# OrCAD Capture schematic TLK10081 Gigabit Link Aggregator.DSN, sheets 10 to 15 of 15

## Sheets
10 S10 CLOCK CONTROL: size B
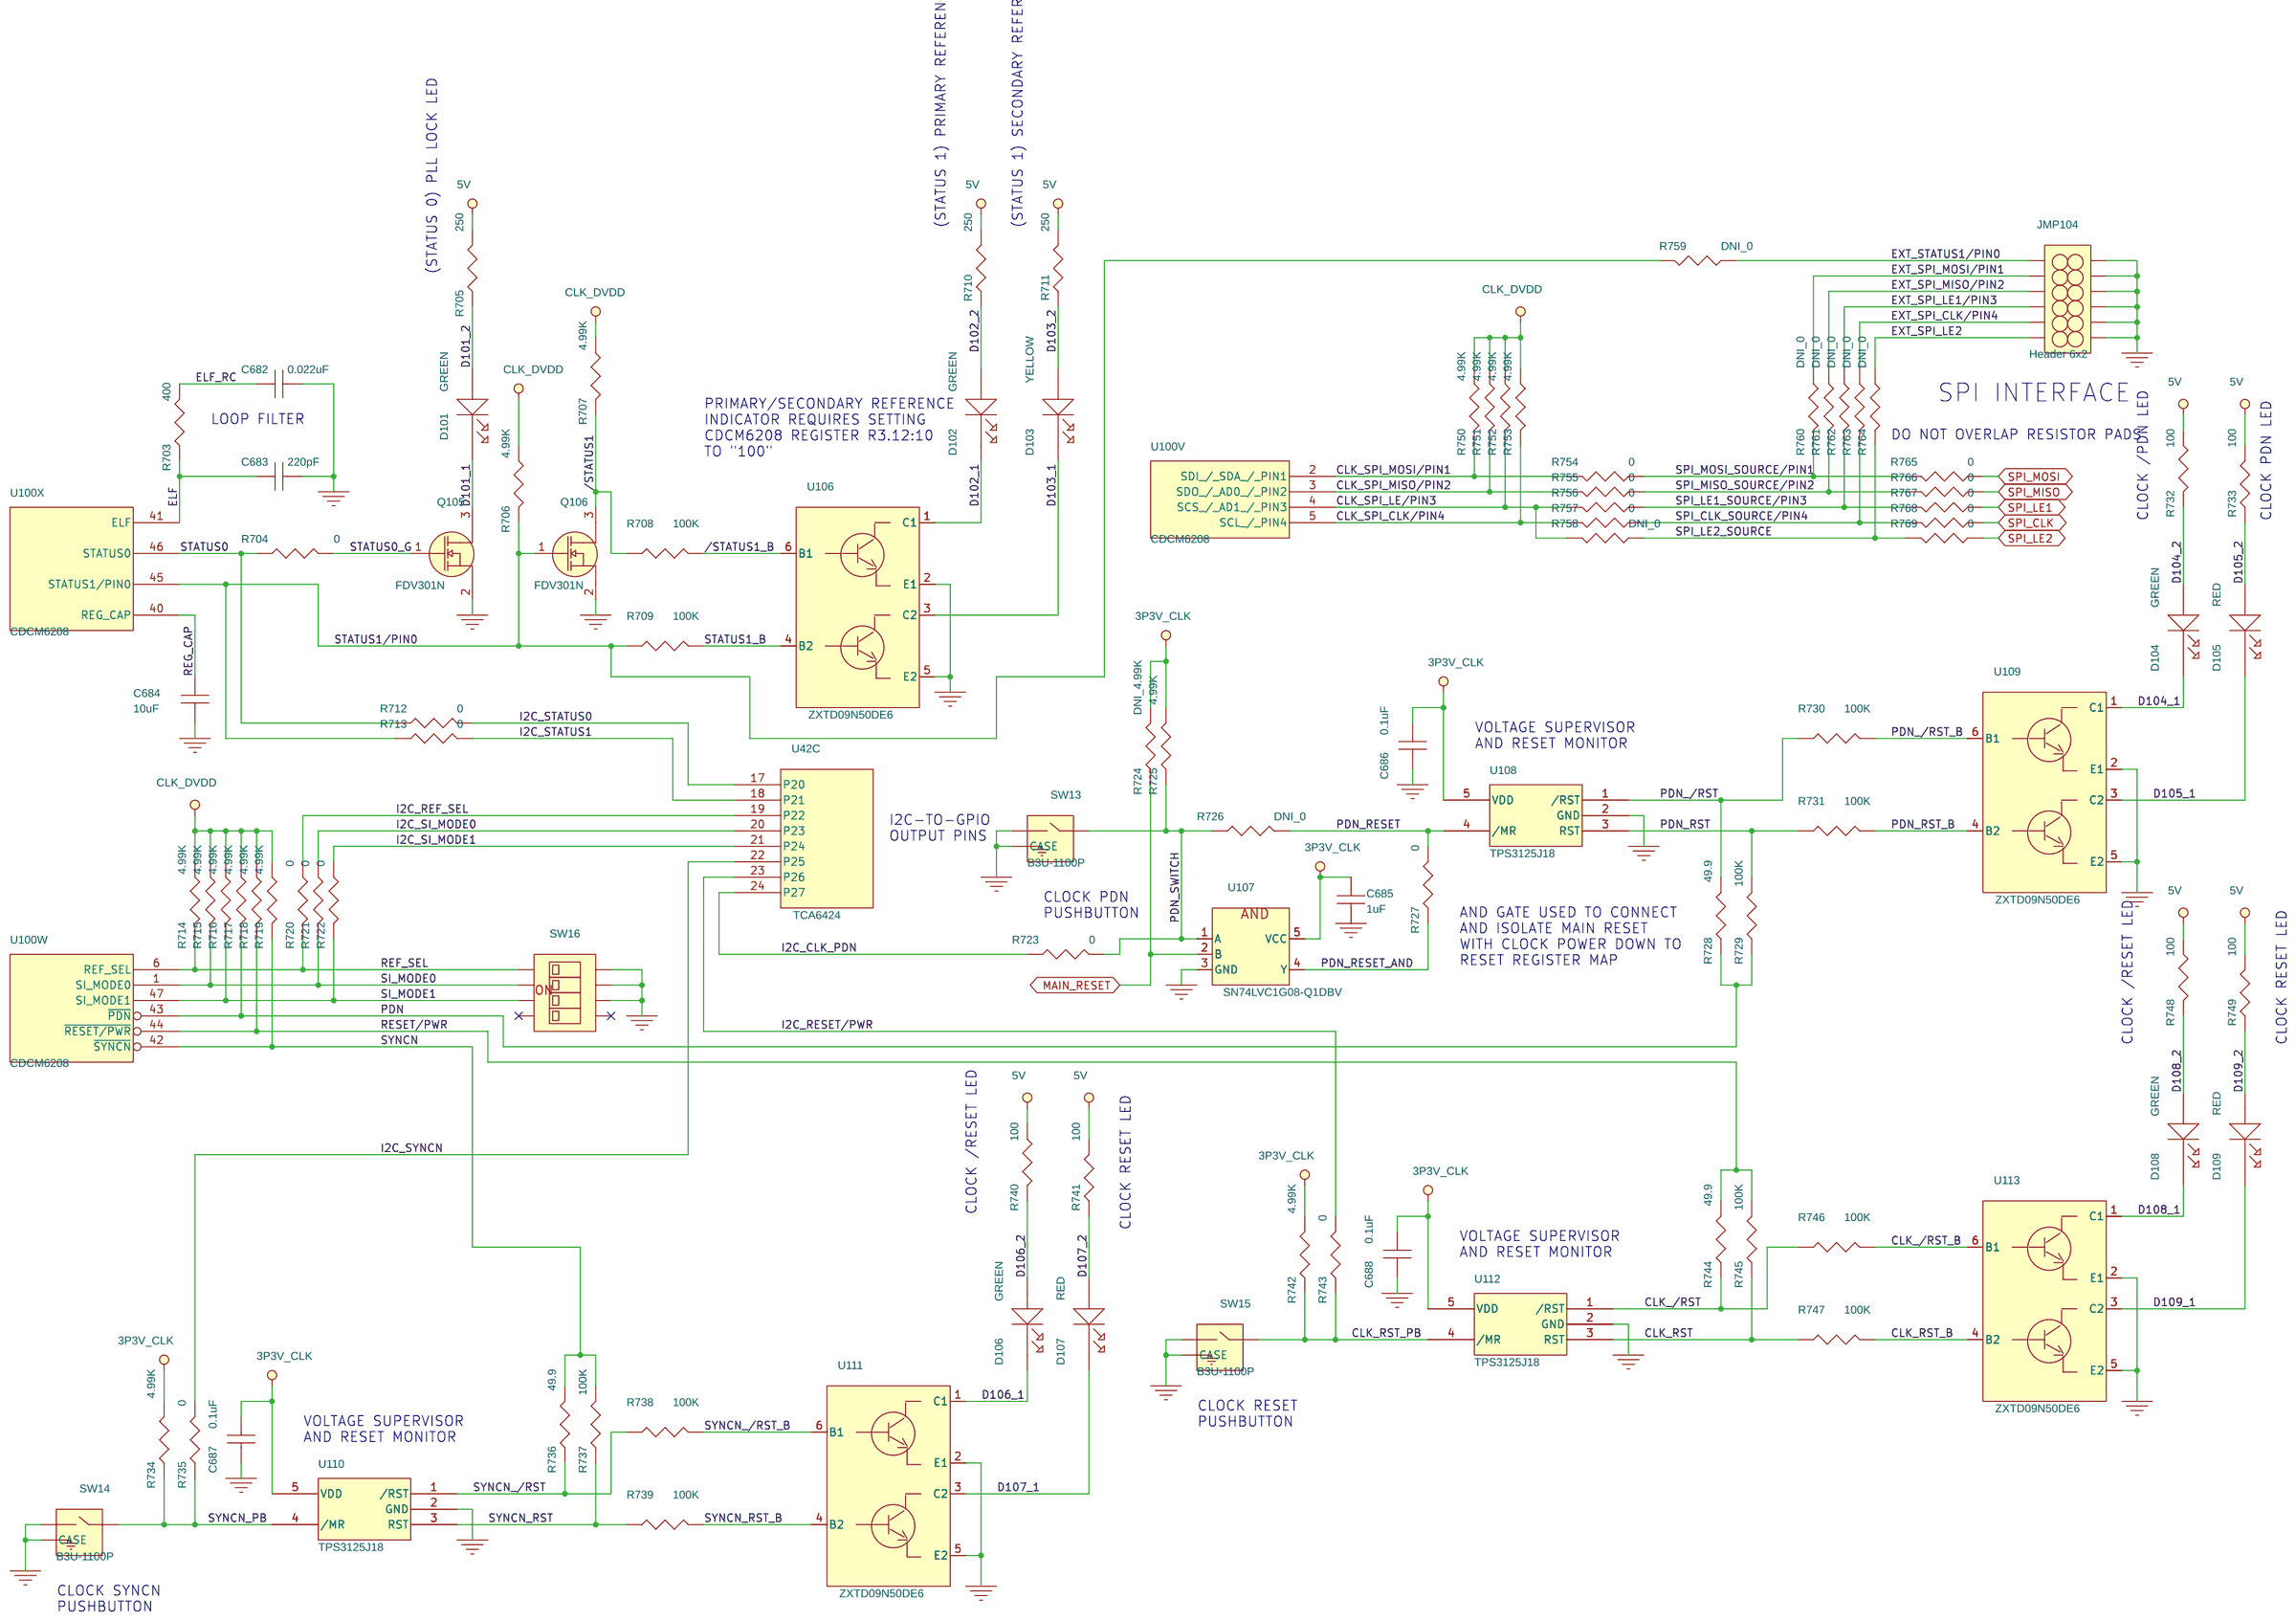
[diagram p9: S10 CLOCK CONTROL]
11 S12 LOW SPEED DATA SIGNALS: size B
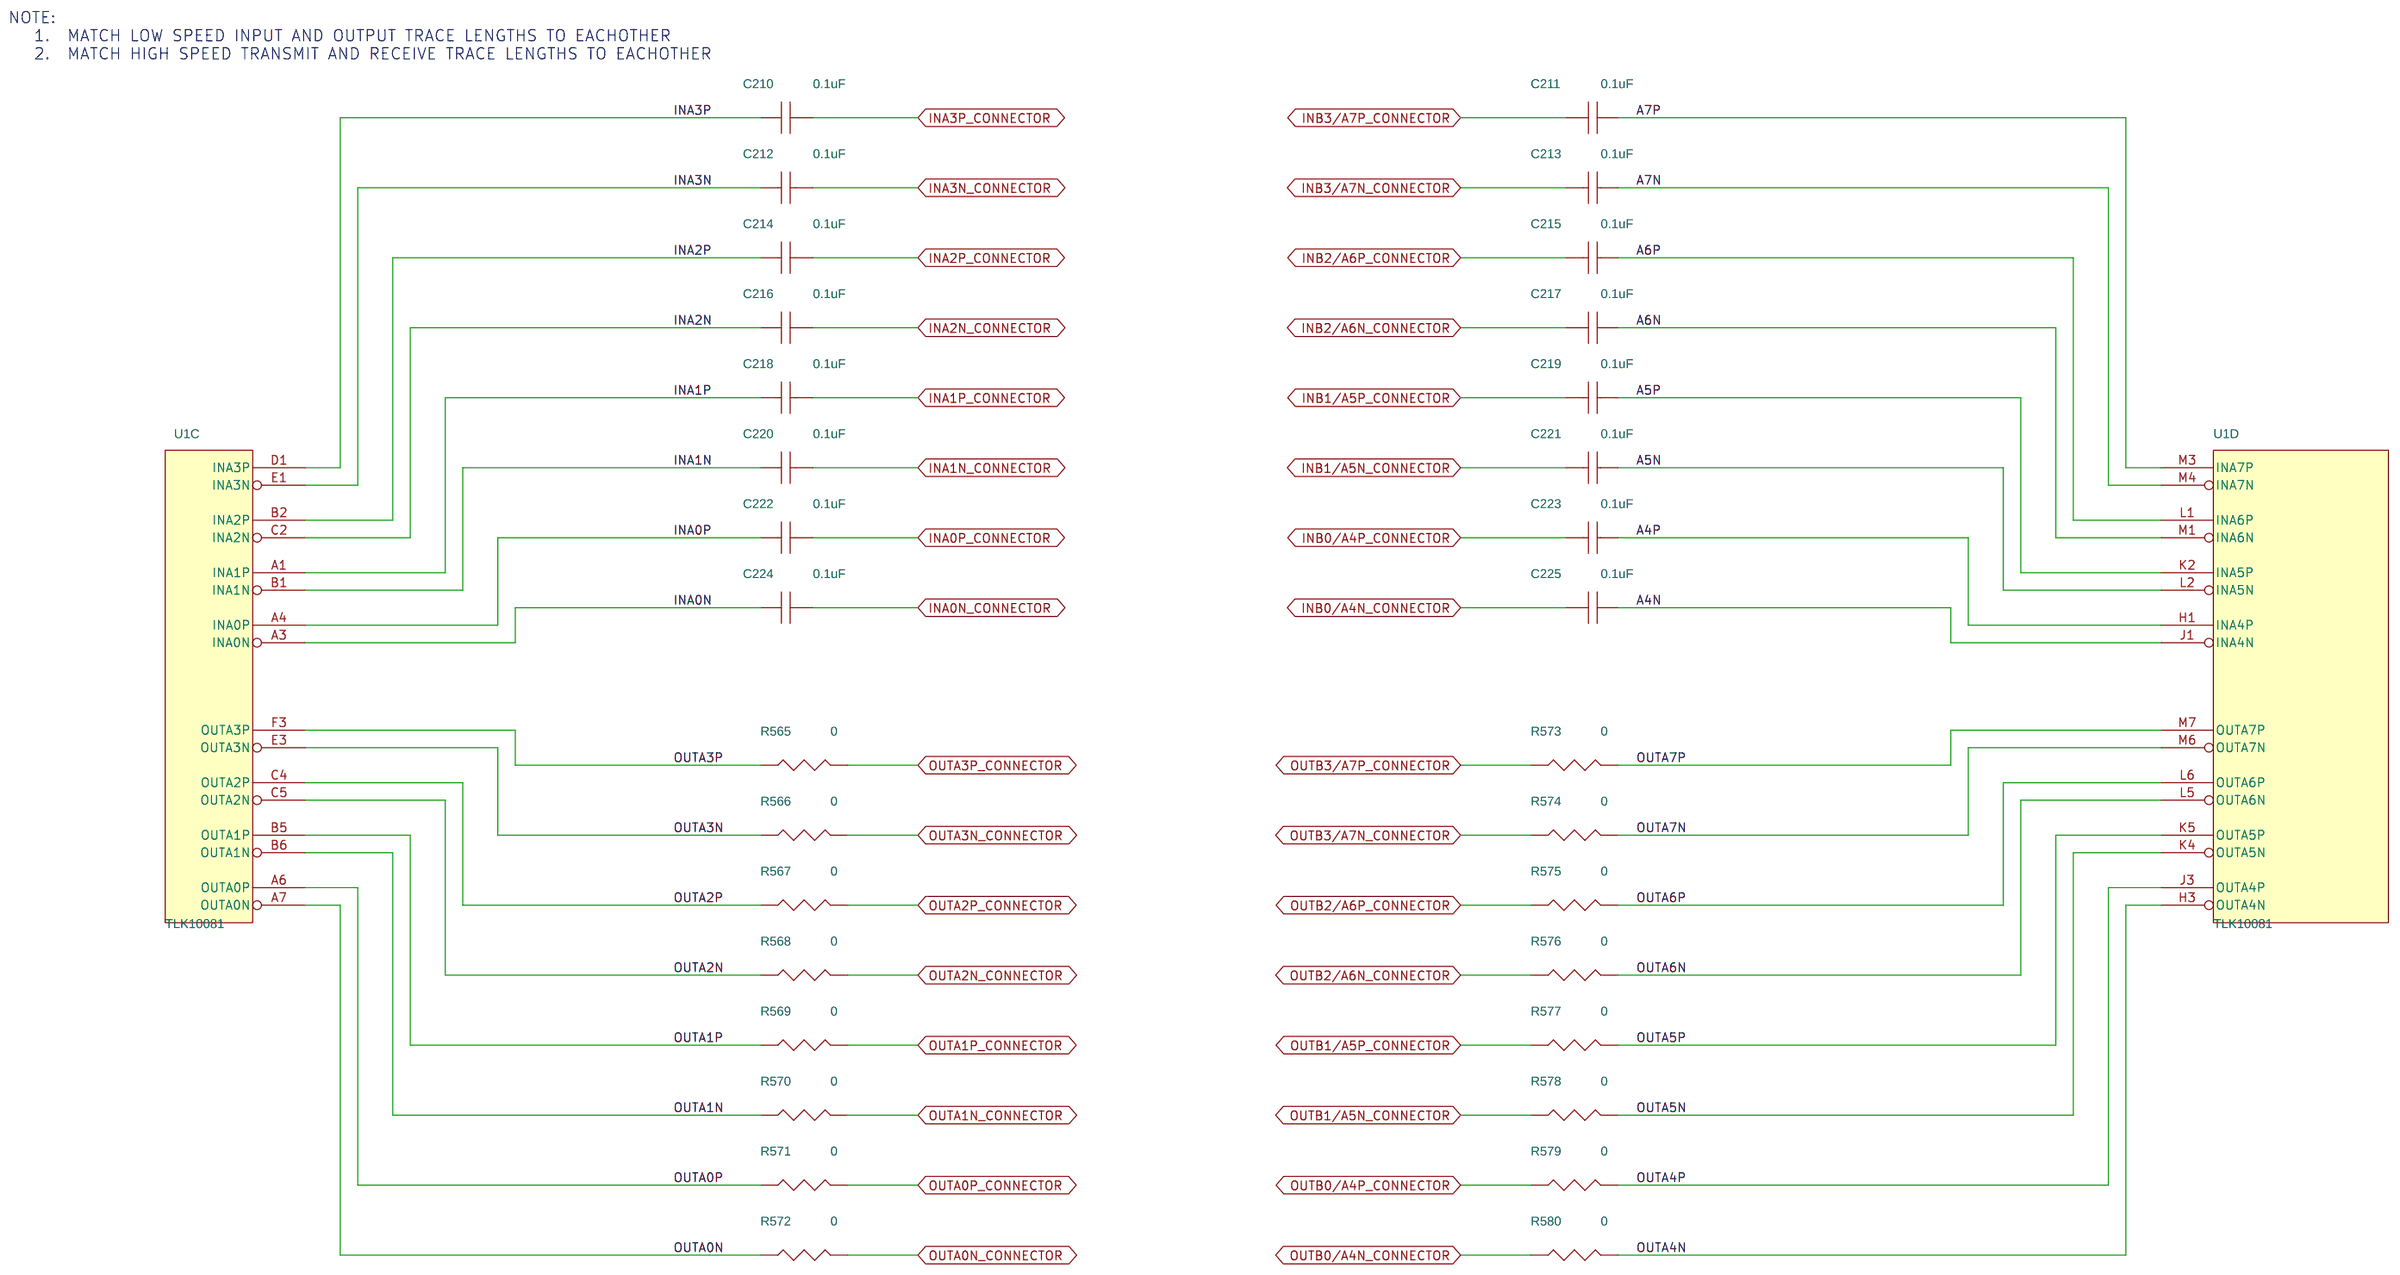
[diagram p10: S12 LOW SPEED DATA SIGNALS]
12 S13 HIGH SPEED DATA SIGNALS: size B
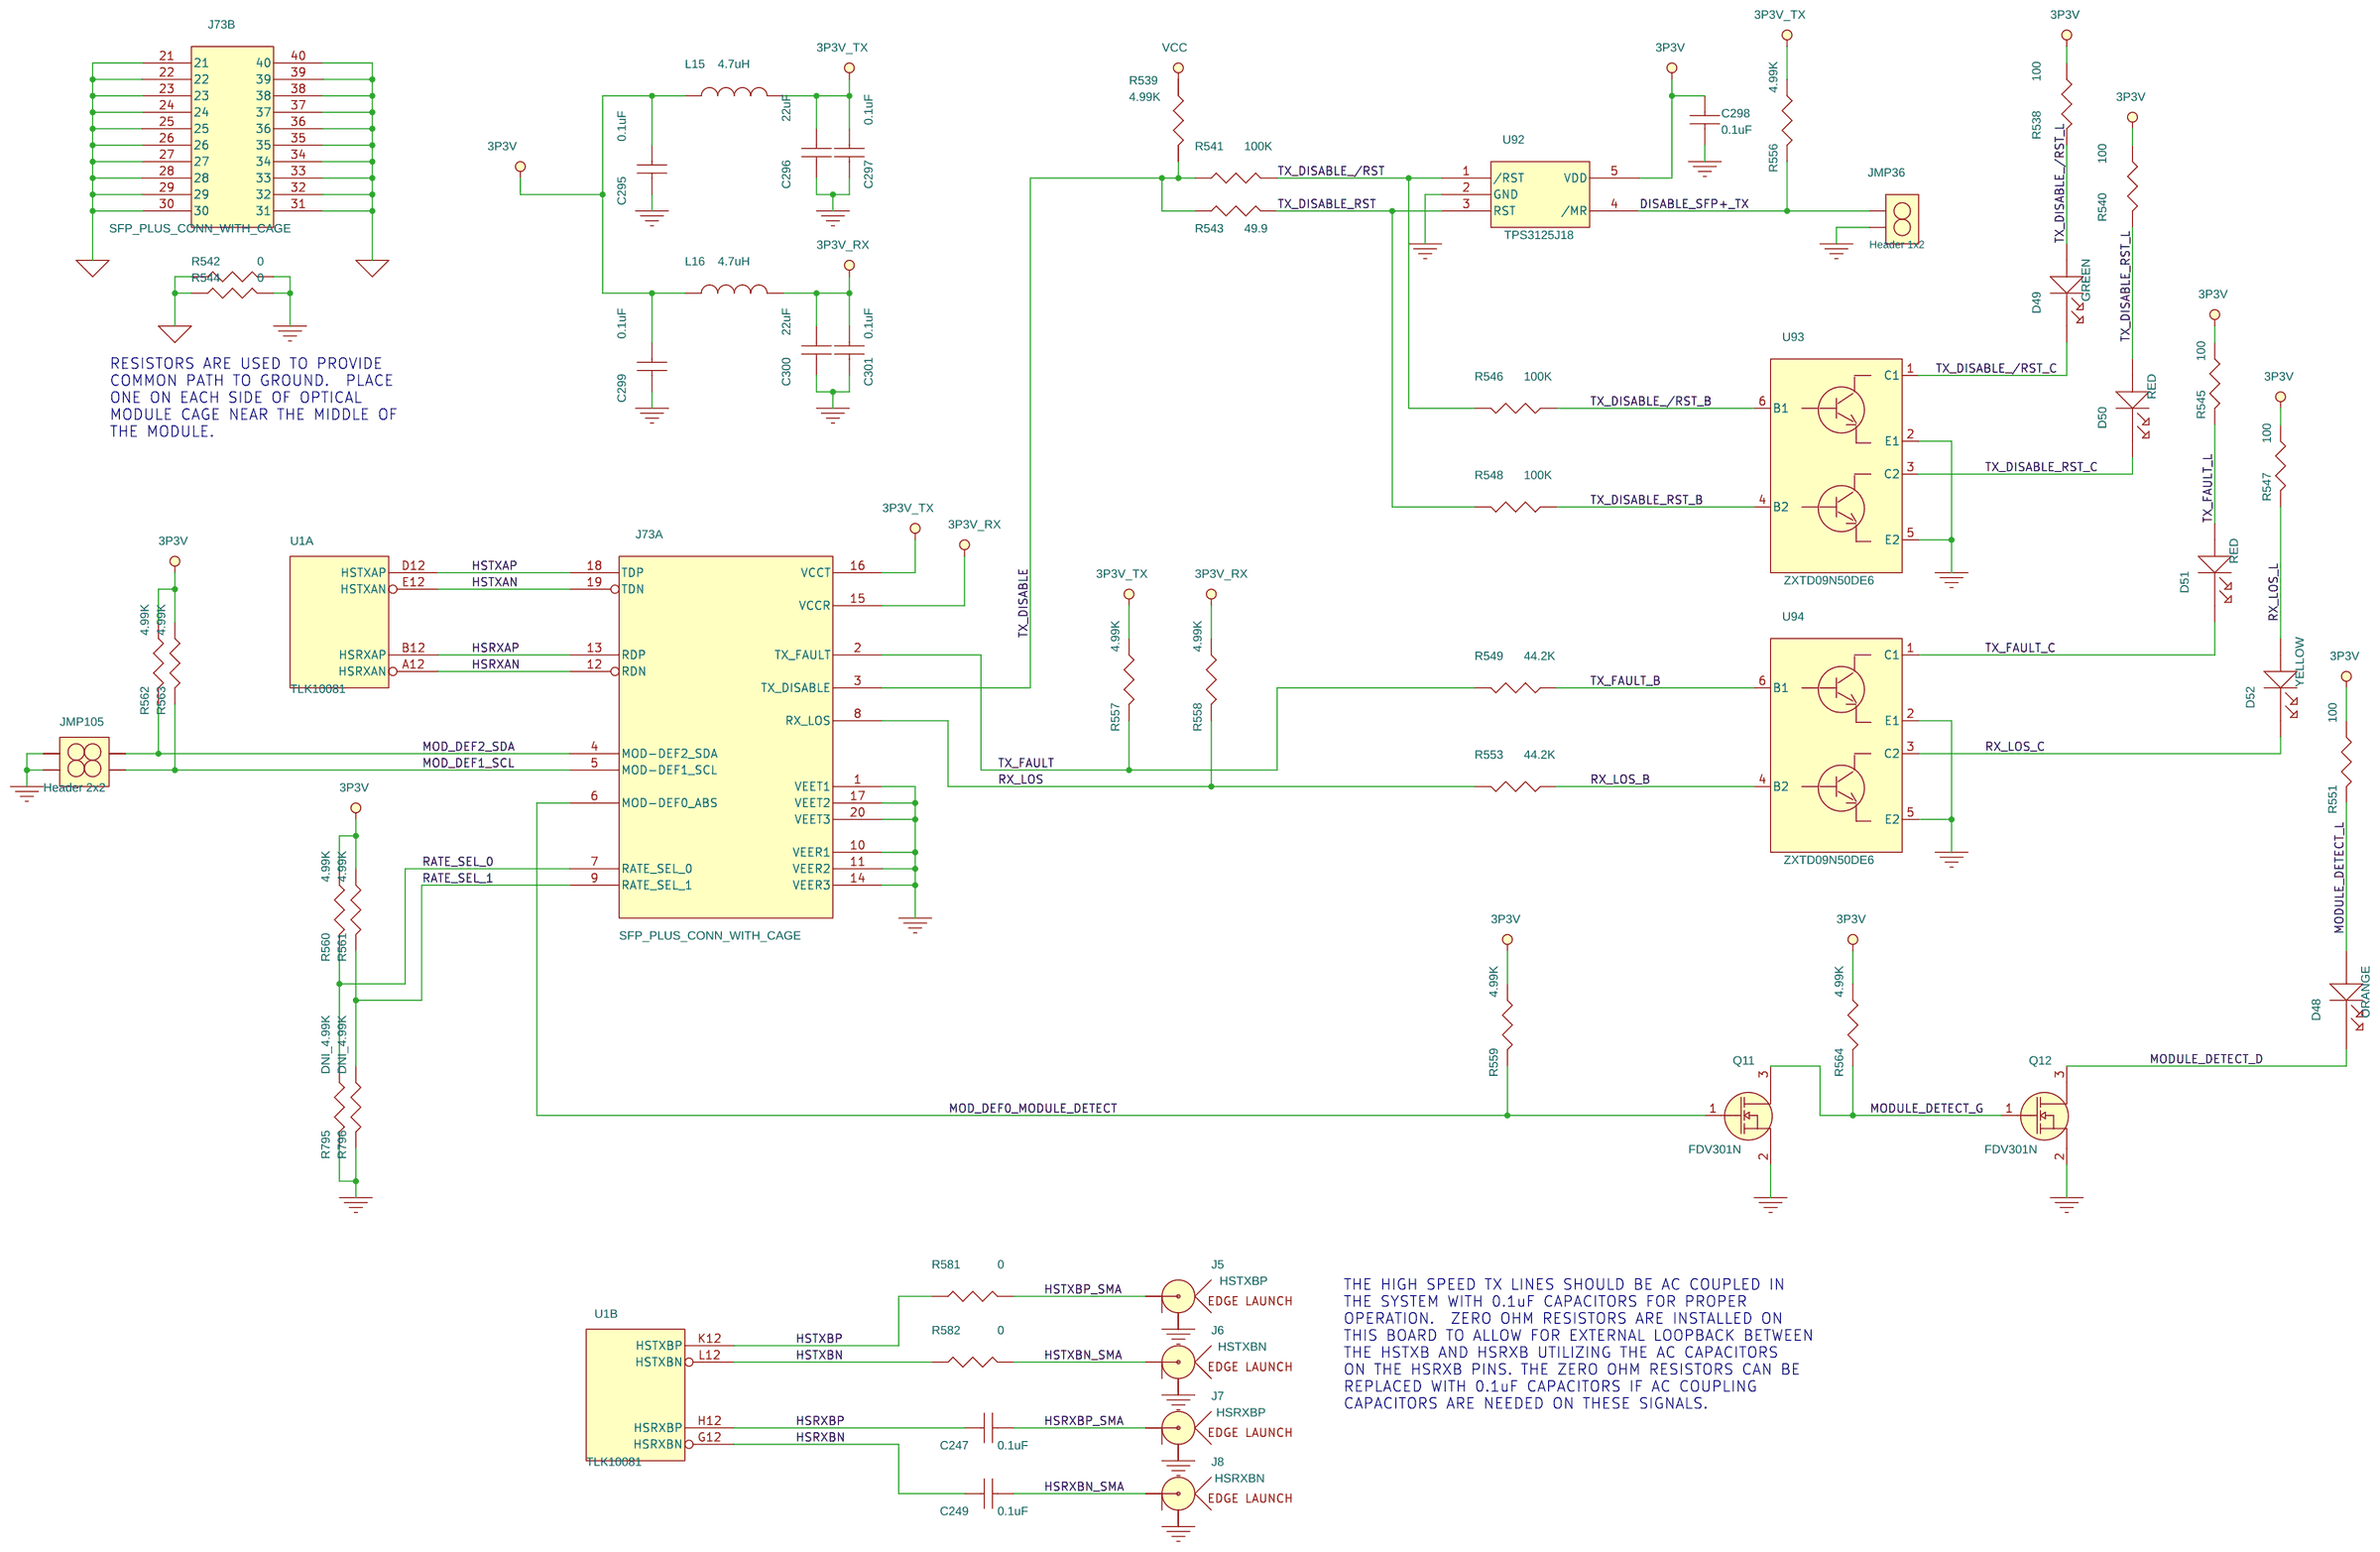
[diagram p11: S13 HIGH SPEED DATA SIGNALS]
13 S11 CRYSTAL OSCILLATORS: size B
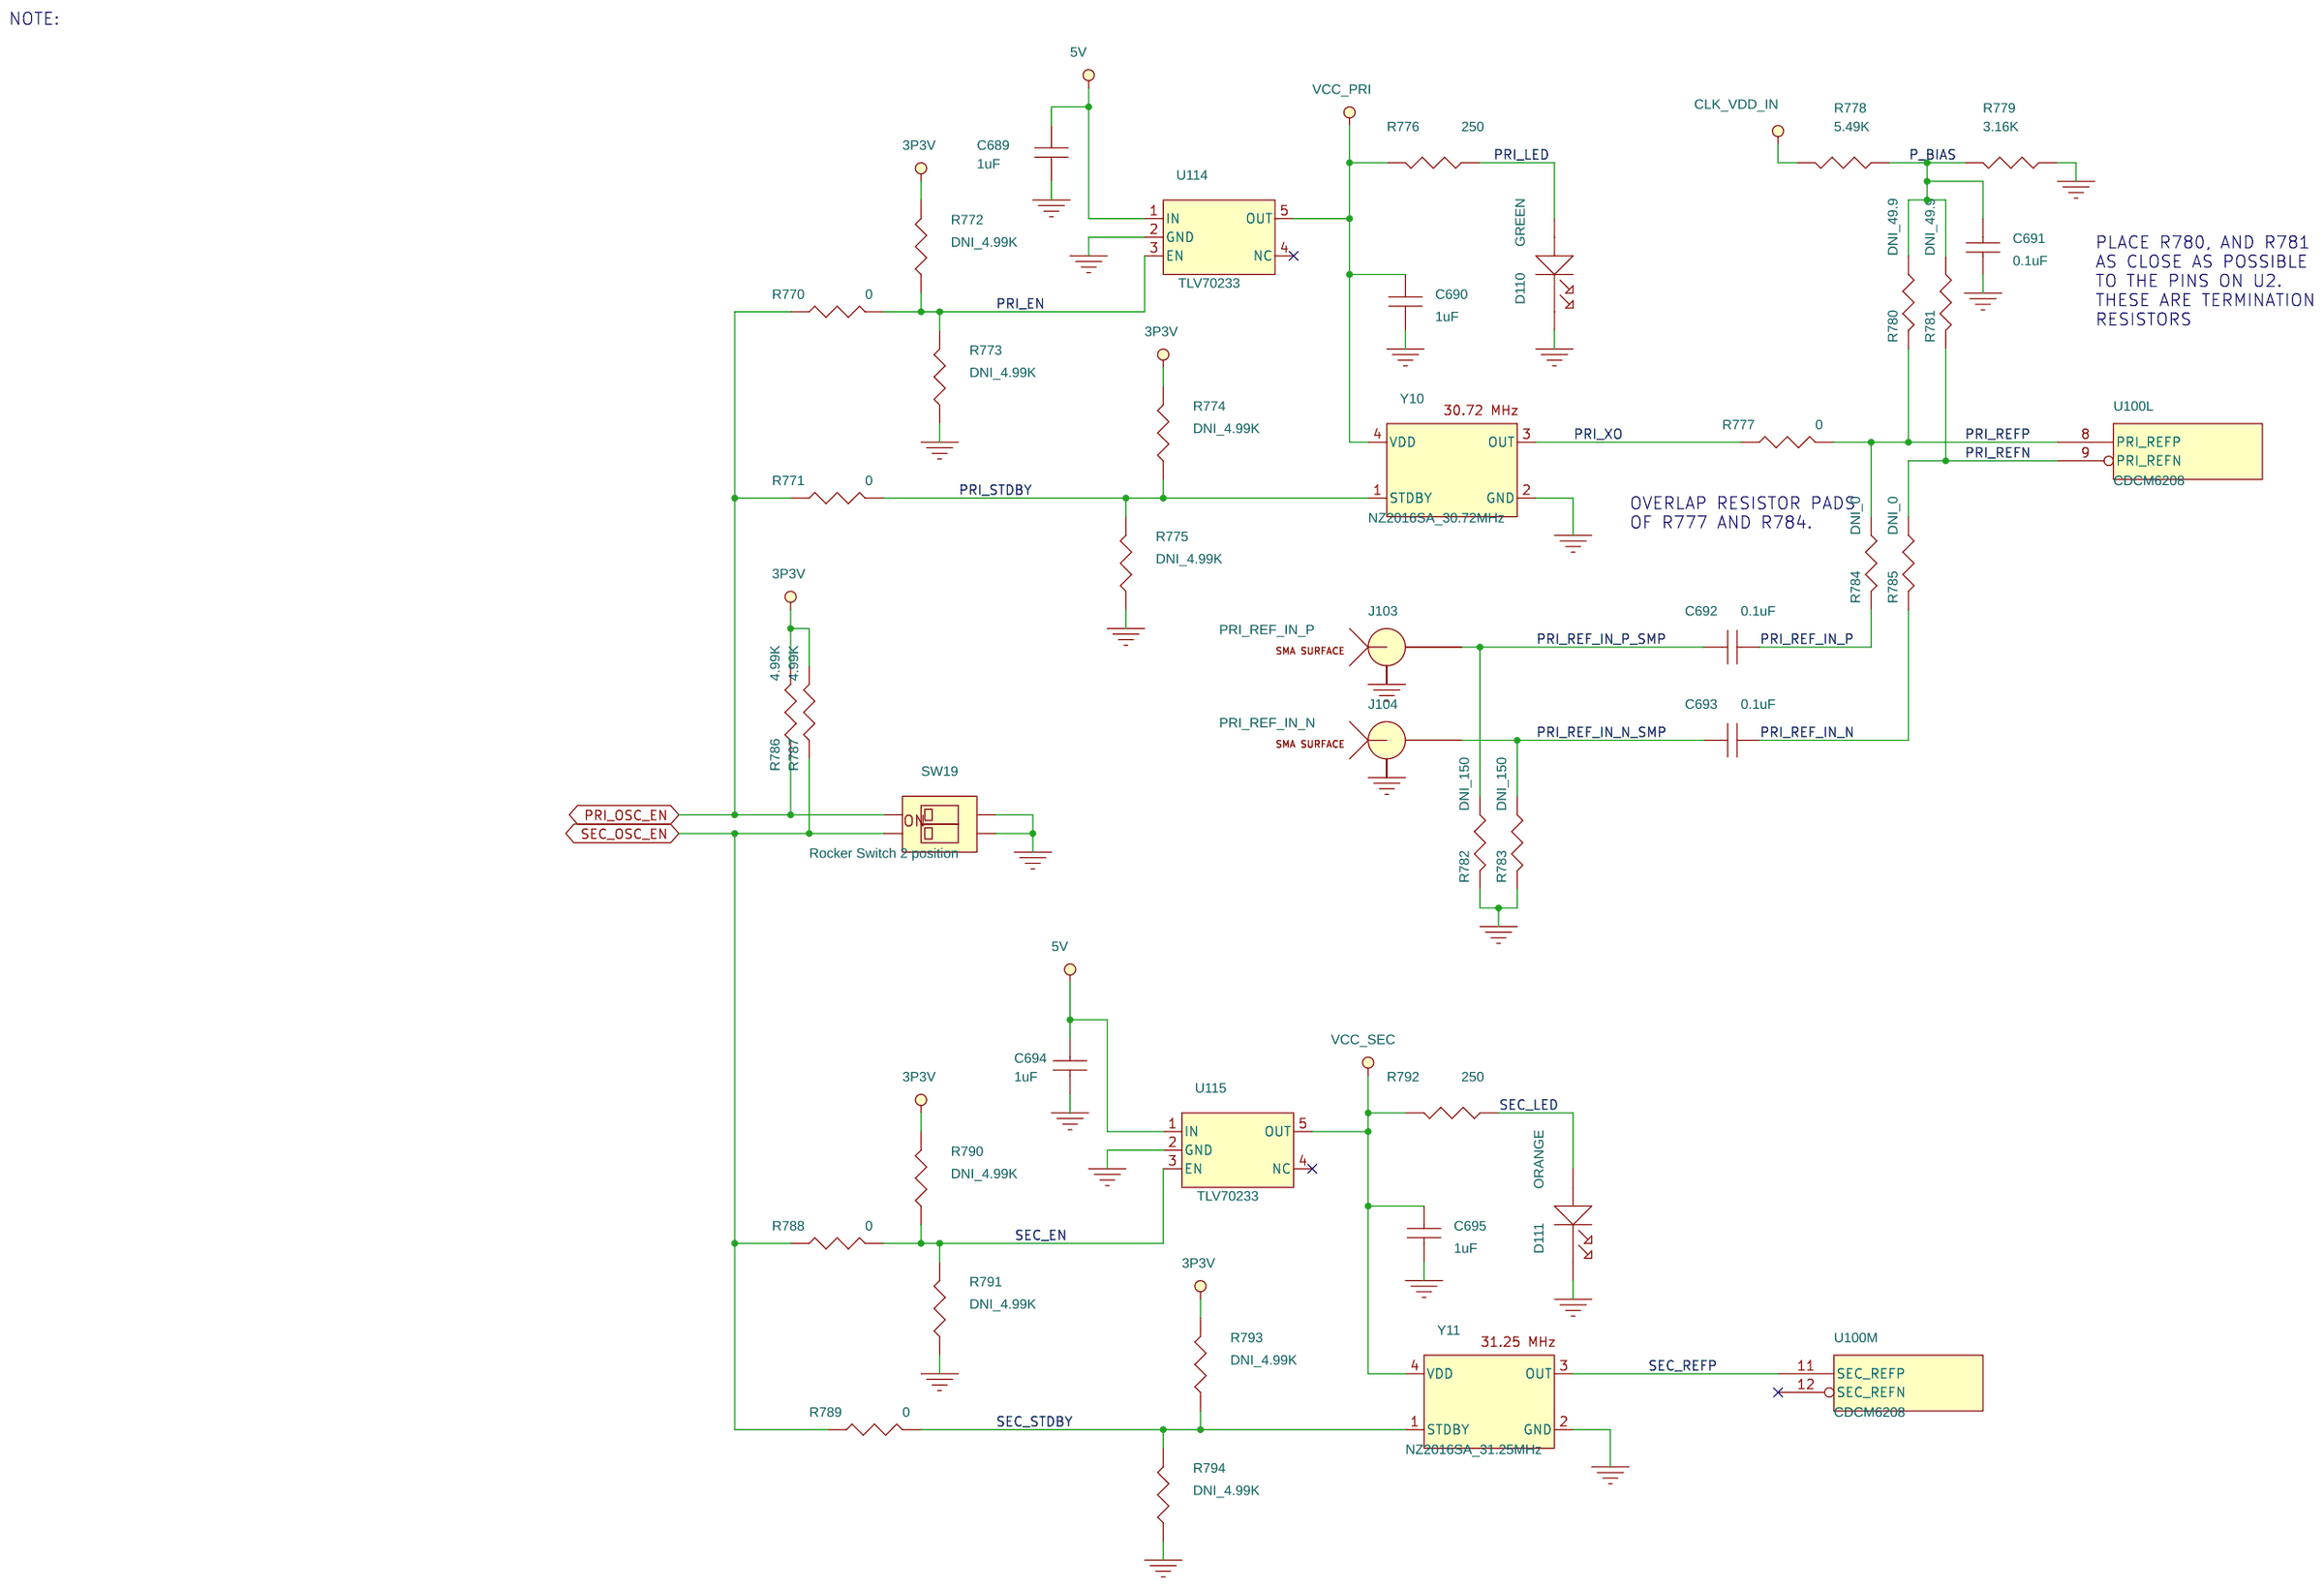
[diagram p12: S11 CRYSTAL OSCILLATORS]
14 S05 VOLTAGE MONITORING: size B
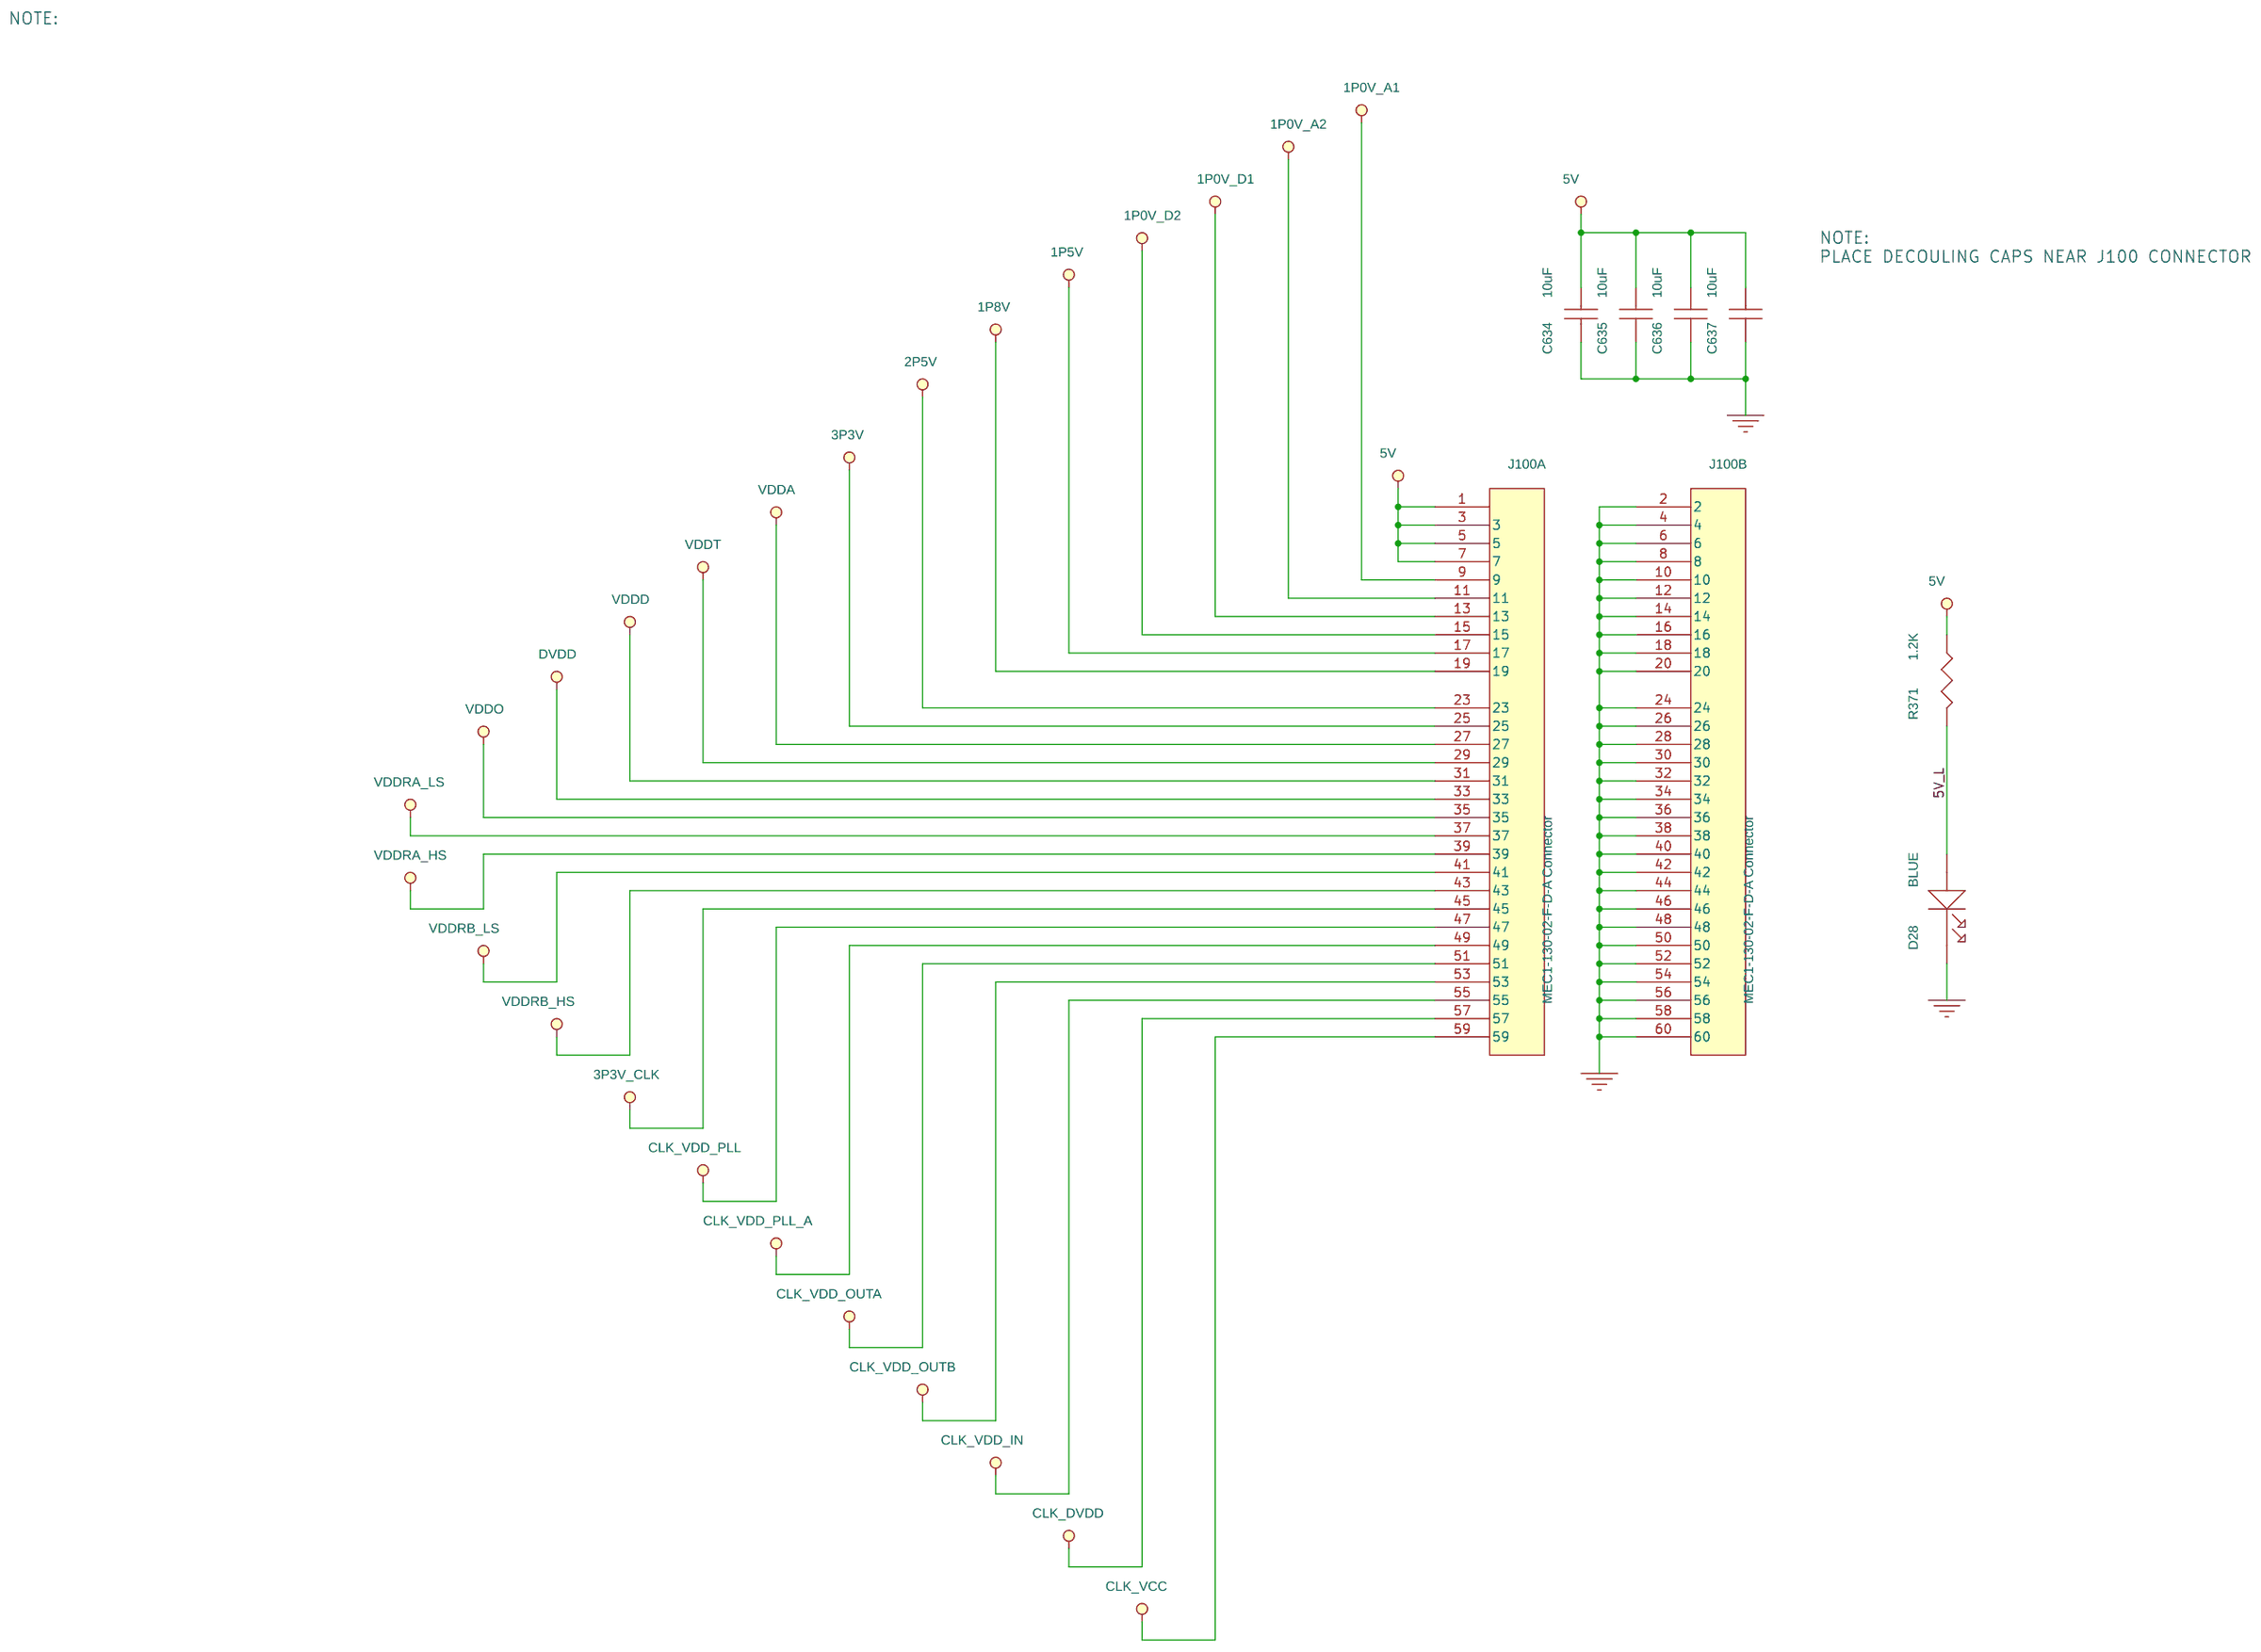
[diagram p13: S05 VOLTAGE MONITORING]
15 S14 BOARD TO BOARD DATA: size B
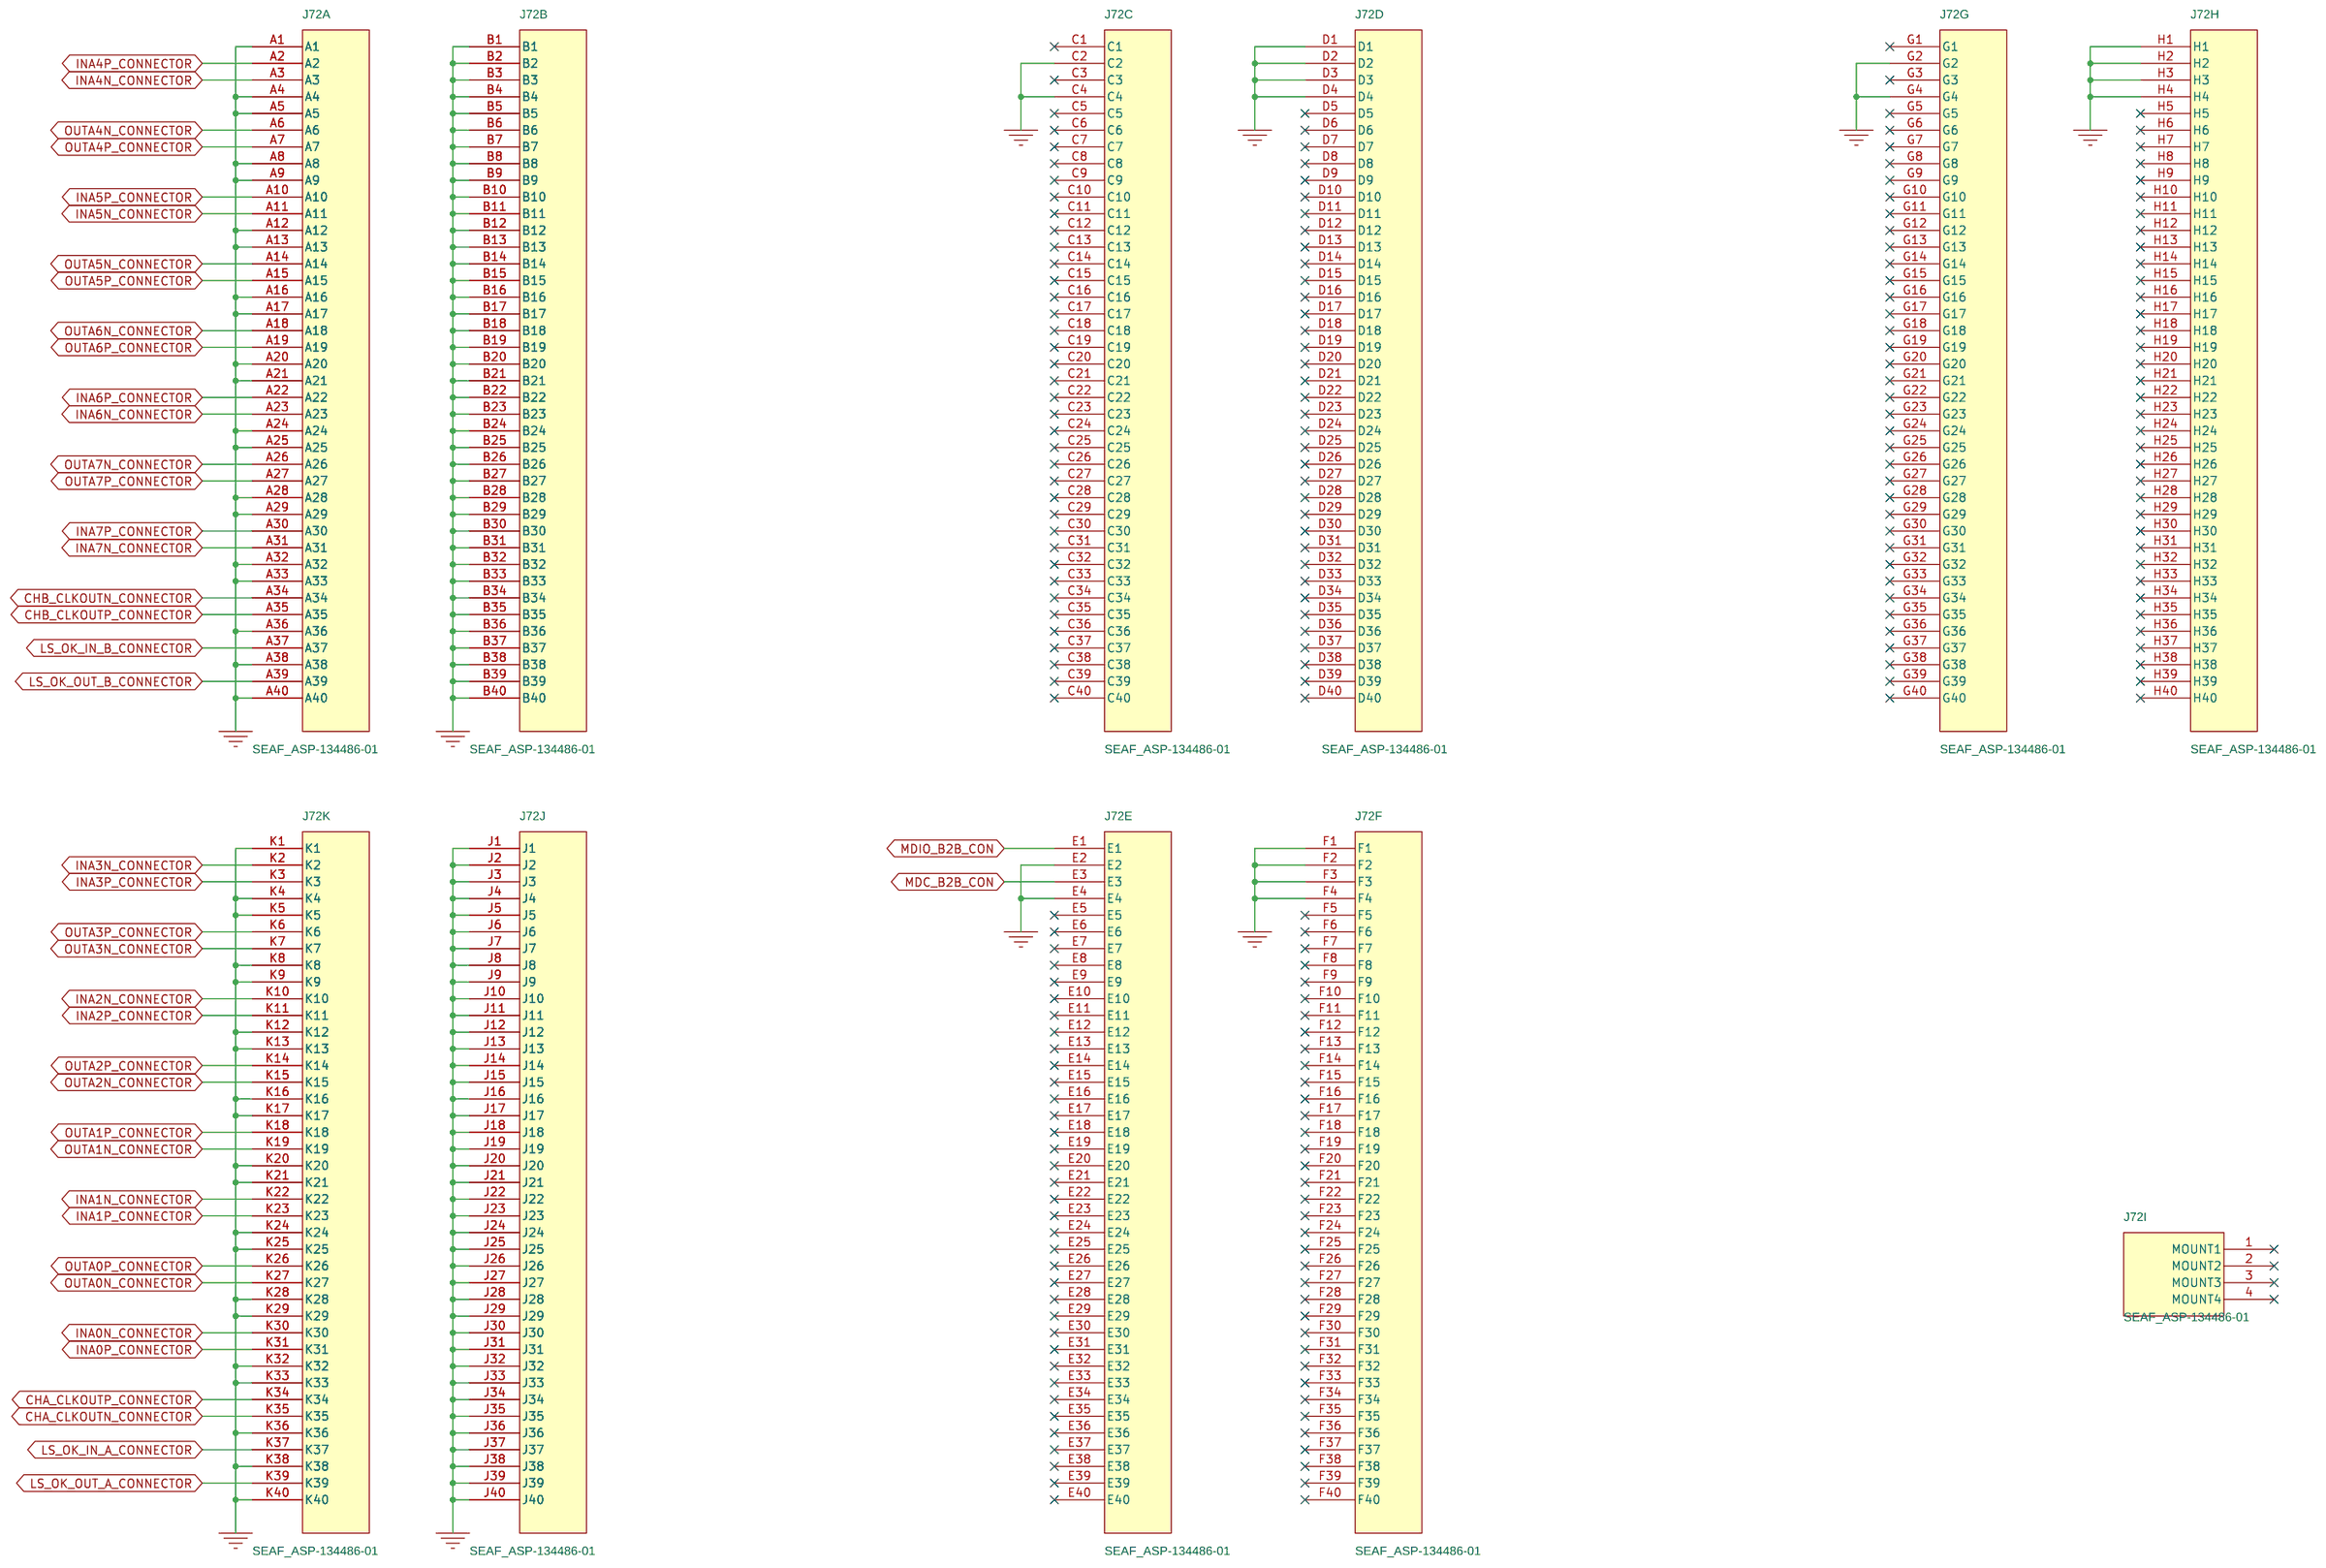
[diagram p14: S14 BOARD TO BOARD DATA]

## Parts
sheet S05 VOLTAGE MONITORING
C634  10uF  [0805]
C635  10uF  [0805]
C636  10uF  [0805]
C637  10uF  [0805]
D28  BLUE  [led_hsmb_c170dra]
J100  MEC1-130-02-F-D-A Connector  [MEC1-130-02-F-D-A]  (sections A,B)
R371  1.2K  [R0603]
sheet S08 MDIO, JTAG, I2C INTERFACE
U1  TLK10081  [ZWQ144]  (sections A,B,C,D,E,F,G,H,I,J,K,L,M,N,O,P,Q,R,S,T,U)
U42  TCA6424  [rgj32]  (sections A,B,C,D)
sheet S10 CLOCK CONTROL
C682  0.022uF  [cc0402]
C683  220pF  [cc0402]
C684  10uF  [cc0402]
C685  1uF  [cc0402]
C686  0.1uF  [cc0603]
C687  0.1uF  [cc0603]
C688  0.1uF  [cc0603]
D101  GREEN  [LED_HSMB_C170DRA]
D102  GREEN  [LED_HSMB_C170DRA]
D103  YELLOW  [led_hsmb_c170dra]
D104  GREEN  [led_hsmb_c170dra]
D105  RED  [led_hsmb_c170dra]
D106  GREEN  [led_hsmb_c170dra]
D107  RED  [led_hsmb_c170dra]
D108  GREEN  [led_hsmb_c170dra]
D109  RED  [led_hsmb_c170dra]
JMP104  Header 6x2  [HDR_THVT_2X6_100]
Q105  FDV301N  [SOT23]
Q106  FDV301N  [SOT23]
R703  400  [r0402]
R704  0  [r0402]
R705  250  [r0402]
R706  4.99K  [r0402]
R707  4.99K  [r0402]
R708  100K  [r0402]
R709  100K  [r0402]
R710  250  [r0402]
R711  250  [r0402]
R712  0  [r0603]
R713  0  [r0603]
R714  4.99K  [r0402]
R715  4.99K  [r0402]
R716  4.99K  [r0402]
R717  4.99K  [r0402]
R718  4.99K  [r0603]
R719  4.99K  [r0603]
R720  0  [r0402]
R721  0  [r0402]
R722  0  [r0402]
R723  0  [r0603]
R724  DNI_4.99K  [r0603]
R725  4.99K  [r0603]
R726  DNI_0  [r0402]
R727  0  [r0402]
R728  49.9  [r0603]
R729  100K  [r0603]
R730  100K  [r0402]
R731  100K  [r0402]
R732  100  [r0603]
R733  100  [r0603]
R734  4.99K  [r0603]
R735  0  [r0603]
R736  49.9  [r0603]
R737  100K  [r0603]
R738  100K  [r0402]
R739  100K  [r0402]
R740  100  [r0603]
R741  100  [r0603]
R742  4.99K  [r0603]
R743  0  [r0603]
R744  49.9  [r0603]
R745  100K  [r0603]
R746  100K  [r0402]
R747  100K  [r0402]
R748  100  [r0603]
R749  100  [r0603]
R750  4.99K  [r0402]
R751  4.99K  [r0402]
R752  4.99K  [r0402]
R753  4.99K  [r0402]
R754  0  [r0402]
R755  0  [r0402]
R756  0  [r0402]
R757  0  [r0402]
R758  DNI_0  [r0402]
R759  DNI_0  [r0402]
R760  DNI_0  [r0402]
R761  DNI_0  [r0402]
R762  DNI_0  [r0402]
R763  DNI_0  [r0402]
R764  DNI_0  [r0402]
R765  0  [r0402]
R766  0  [r0402]
R767  0  [r0402]
R768  0  [r0402]
R769  0  [r0402]
SW13  B3U-1100P  [OMRON_3PIN_US_B3U-1100P]
SW14  B3U-1100P  [OMRON_3PIN_US_B3U-1100P]
SW15  B3U-1100P  [OMRON_3PIN_US_B3U-1100P]
SW16  Rocker Switch 4 position  [gdh04s_thomasbetts]
U106  ZXTD09N50DE6  [DDC6]
U107  SN74LVC1G08-Q1DBV  [DBV]
U108  TPS3125J18  [SOT23_5pin]
U109  ZXTD09N50DE6  [DDC6]
U110  TPS3125J18  [SOT23_5pin]
U111  ZXTD09N50DE6  [DDC6]
U112  TPS3125J18  [SOT23_5pin]
U113  ZXTD09N50DE6  [DDC6]
sheet S11 CRYSTAL OSCILLATORS
C689  1uF  [cc0402]
C690  1uF  [cc0201]
C691  0.1uF  [cc0201]
C692  0.1uF  [cc0201]
C693  0.1uF  [cc0201]
C694  1uF  [cc0402]
C695  1uF  [cc0201]
D110  GREEN  [LED_HSMB_C170DRA]
D111  ORANGE  [LED_HSMB_C170DRA]
J103  PRI_REF_IN_P  [32k141-40m-fr4wvia]
J104  PRI_REF_IN_N  [32k141-40m-fr4wvia]
R770  0  [r0402]
R771  0  [r0402]
R772  DNI_4.99K  [r0402]
R773  DNI_4.99K  [r0402]
R774  DNI_4.99K  [r0402]
R775  DNI_4.99K  [r0402]
R776  250  [r0402]
R777  0  [r0201]
R778  5.49K  [r0201]
R779  3.16K  [r0201]
R780  DNI_49.9  [r0201]
R781  DNI_49.9  [r0201]
R782  DNI_150  [r0201]
R783  DNI_150  [r0201]
R784  DNI_0  [r0201]
R785  DNI_0  [r0201]
R786  4.99K  [r0402]
R787  4.99K  [r0402]
R788  0  [r0402]
R789  0  [r0402]
R790  DNI_4.99K  [r0402]
R791  DNI_4.99K  [r0402]
R792  250  [r0402]
R793  DNI_4.99K  [r0402]
R794  DNI_4.99K  [r0402]
SW19  Rocker Switch 2 position  [gdh02s_thomasbetts]
U100  CDCM6208  [hqfn_48_282x282_20]  (sections A,B,C,D,E,F,G,H,I,J,K,L,M,N,O,P,Q,R,S,T,U,V,W,X)
U114  TLV70233  [SOT23_5pin]
U115  TLV70233  [SOT23_5pin]
Y10  NZ2016SA_30.72MHz  [NZ2016SA-ICXO]
Y11  NZ2016SA_31.25MHz  [NZ2016SA-ICXO]
sheet S12 LOW SPEED DATA SIGNALS
C210  0.1uF  [cc0201]
C211  0.1uF  [cc0201]
C212  0.1uF  [cc0201]
C213  0.1uF  [cc0201]
C214  0.1uF  [cc0201]
C215  0.1uF  [cc0201]
C216  0.1uF  [cc0201]
C217  0.1uF  [cc0201]
C218  0.1uF  [cc0201]
C219  0.1uF  [cc0201]
C220  0.1uF  [cc0201]
C221  0.1uF  [cc0201]
C222  0.1uF  [cc0201]
C223  0.1uF  [cc0201]
C224  0.1uF  [cc0201]
C225  0.1uF  [cc0201]
R565  0  [r0201]
R566  0  [r0201]
R567  0  [r0201]
R568  0  [r0201]
R569  0  [r0201]
R570  0  [r0201]
R571  0  [r0201]
R572  0  [r0201]
R573  0  [r0201]
R574  0  [r0201]
R575  0  [r0201]
R576  0  [r0201]
R577  0  [r0201]
R578  0  [r0201]
R579  0  [r0201]
R580  0  [r0201]
sheet S13 HIGH SPEED DATA SIGNALS
C247  0.1uF  [cc0201]
C249  0.1uF  [cc0201]
C295  0.1uF  [cc0402]
C296  22uF  [cc0805]
C297  0.1uF  [cc0402]
C298  0.1uF  [cc0402]
C299  0.1uF  [cc0402]
C300  22uF  [cc0805]
C301  0.1uF  [cc0402]
D48  ORANGE  [LED_HSMB_C170DRA]
D49  GREEN  [LED_HSMB_C170DRA]
D50  RED  [LED_HSMB_C170DRA]
D51  RED  [LED_HSMB_C170DRA]
D52  YELLOW  [LED_HSMB_C170DRA]
J5  HSTXBP  [CON_32K243-40M]
J6  HSTXBN  [CON_32K243-40M]
J7  HSRXBP  [CON_32K243-40M]
J8  HSRXBN  [CON_32K243-40M]
J73  SFP_PLUS_CONN_WITH_CAGE  [AMP_SFPCAGE_WIDECHANNEL]  (sections A,B)
JMP36  Header 1x2  [HDR_THVT_1X2_100]
JMP105  Header 2x2  [HDR_THVT_2X2_100]
L15  4.7uH  [1210]
L16  4.7uH  [1210]
Q11  FDV301N  [SOT23]
Q12  FDV301N  [SOT23]
R538  100  [r0603]
R539  4.99K  [r0603]
R540  100  [r0603]
R541  100K  [r0603]
R542  0  [r0805]
R543  49.9  [r0603]
R544  0  [r0805]
R545  100  [r0603]
R546  100K  [r0402]
R547  100  [r0603]
R548  100K  [r0402]
R549  44.2K  [r0402]
R551  100  [r0402]
R553  44.2K  [r0402]
R556  4.99K  [r0402]
R557  4.99K  [r0402]
R558  4.99K  [r0402]
R559  4.99K  [r0402]
R560  4.99K  [r0402]
R561  4.99K  [r0402]
R562  4.99K  [r0402]
R563  4.99K  [r0402]
R564  4.99K  [r0402]
R581  0  [r0201]
R582  0  [r0201]
R795  DNI_4.99K  [r0402]
R796  DNI_4.99K  [r0402]
U92  TPS3125J18  [SOT23_5pin]
U93  ZXTD09N50DE6  [DDC6]
U94  ZXTD09N50DE6  [DDC6]
sheet S14 BOARD TO BOARD DATA
J72  SEAF_ASP-134486-01  [ASP-134486]  (sections A,B,C,D,E,F,G,H,I,J,K)

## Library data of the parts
C634 = CAP_NP: Vendor: Digi-Key
C635 = NPCap1206_1.0uf
C636 = NPCap1206_0.1uf
C637 = NPCap0805_0.01uf
D28 = LED_HSMB: Mfr_Part_Number: HSMR-C170
J100 = MEC1-130-02-F-D-A_Connector
R371 R538-R541 R543 R545 R547 = r0603
U1 = TLK10081
U42 = TCA6424_0
C210-C225 C247 C249 C295 C297 C299 C301 C682-C684 C686-C695 = cc0402
C298 C685 = CAP_NP
D101 D102 = LED_HSMG
D52 D103 = LED_HSMY: Mfr_Part_Number: HSMY-C170
D49 D104 D106 D108 D110 = LED_HSMG: Mfr_Part_Number: HSMG-C170
D50 D51 D105 D107 D109 = LED_HSMS: Mfr_Part_Number: HSMS-C170
JMP104 = Header_6x2
Q11 Q12 Q105 Q106 = FDV301N_NFET_1
R542 R544 R546 R548 R549 R551 R553 R556-R564 R703-R796 = r0402
SW13-SW15 = B3U-1100P
SW16 = Rocker_Switch_4_position_0
U93 U94 U106 U109 U111 U113 = ZXTD09N50DE6
U107 = SN74LVC1G08-Q1DBV
U108 U110 U112 = TPS3125J18
D48 D111 = LED_HSMD: Mfr_Part_Number: HSMD-C170
J103 J104 = sma_surface
SW19 = Rocker_Switch_2_position
U100 = CDCM6208
U114 U115 = TLV713
Y10 = NZ2016SA_30.72MHz
Y11 = NZ2016SA_31.25MHz
R565-R582 = r0201
C296 C300 = cc0805
J5-J8 = Edge_Launch_SMA_0
J73 = SFP_PLUS_CONN_WITH_CAGE
JMP36 = 2_Pin_Berg_Jumper
JMP105 = Header_2x2
L15 L16 = Inductor_1210
U92 = TPS3125J18_0
J72 = SEAF_ASP-134486-01_0

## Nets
5V: C634.1 C635.1 C636.1 C637.1 C689.1 C694.1 J100.1 J100.3 J100.5 J100.7 R371.1 R705.2 R710.2 R711.2 R732.1 R733.1 R740.1 R741.1 R748.1 R749.1 U114.1(IN) U115.1(IN) ; also on sheet 3 4 5 7 8
5V_L: D28.2 R371.2
DVDD: J100.33 ; also on sheet 5 6
GND: C295.2 C296.2 C297.2 C298.2 C299.2 C300.2 C301.2 C634.2 C635.2 C636.2 C637.2 C682.2 C683.2 C684.2 C685.2 C686.2 C687.2 C688.2 C689.2 C690.2 C691.1 C694.2 C695.2 D28.1 D110.1 D111.1 J5.2(SHIELD1) J5.3(SHIELD2) J6.2(SHIELD1) J6.3(SHIELD2) J7.2(SHIELD1) J7.3(SHIELD2) J8.2(SHIELD1) J8.3(SHIELD2) J72.A1 J72.A4 J72.A5 J72.A8 J72.A9 J72.A12 J72.A13 J72.A16 J72.A17 J72.A20 J72.A21 J72.A24 J72.A25 J72.A28 J72.A29 J72.A32 J72.A33 J72.A36 J72.A38 J72.A40 J72.B1 J72.B2 J72.B3 J72.B4 J72.B5 J72.B6 J72.B7 J72.B8 J72.B9 J72.B10 J72.B11 J72.B12 J72.B13 J72.B14 J72.B15 J72.B16 J72.B17 J72.B18 J72.B19 J72.B20 J72.B21 J72.B22 J72.B23 J72.B24 J72.B25 J72.B26 J72.B27 J72.B28 J72.B29 J72.B30 J72.B31 J72.B32 J72.B33 J72.B34 J72.B35 J72.B36 J72.B37 J72.B38 J72.B39 J72.B40 J72.C2 J72.C4 J72.D1 J72.D2 J72.D3 J72.D4 J72.E2 J72.E4 J72.F1 J72.F2 J72.F3 J72.F4 J72.G2 J72.G4 J72.H1 J72.H2 J72.H3 J72.H4 J72.J1 J72.J2 J72.J3 J72.J4 J72.J5 J72.J6 J72.J7 J72.J8 J72.J9 J72.J10 J72.J11 J72.J12 J72.J13 J72.J14 J72.J15 J72.J16 J72.J17 J72.J18 J72.J19 J72.J20 J72.J21 J72.J22 J72.J23 J72.J24 J72.J25 J72.J26 J72.J27 J72.J28 J72.J29 J72.J30 J72.J31 J72.J32 J72.J33 J72.J34 J72.J35 J72.J36 J72.J37 J72.J38 J72.J39 J72.J40 J72.K1 J72.K4 J72.K5 J72.K8 J72.K9 J72.K12 J72.K13 J72.K16 J72.K17 J72.K20 J72.K21 J72.K24 J72.K25 J72.K28 J72.K29 J72.K32 J72.K33 J72.K36 J72.K38 J72.K40 J73.1(VEET1) J73.10(VEER1) J73.11(VEER2) J73.14(VEER3) J73.17(VEET2) J73.20(VEET3) J100.2 J100.4 J100.6 J100.8 J100.10 J100.12 J100.14 J100.16 J100.18 J100.20 J100.24 J100.26 J100.28 J100.30 J100.32 J100.34 J100.36 J100.38 J100.40 J100.42 J100.44 J100.46 J100.48 J100.50 J100.52 J100.54 J100.56 J100.58 J100.60 J103.2 J103.3 J103.4 J103.5 J104.2 J104.3 J104.4 J104.5 JMP36.2 JMP104.2 JMP104.4 JMP104.6 JMP104.8 JMP104.10 JMP104.12 JMP105.2 JMP105.4 Q11.2(S) Q12.2(S) Q105.2(S) Q106.2(S) R542.2 R544.2 R773.1 R775.1 R779.1 R782.2 R783.2 R791.1 R794.1 R795.2 R796.2 SW13.2 SW13.3(CASE) SW14.2 SW14.3(CASE) SW15.2 SW15.3(CASE) SW16.2 SW16.4 SW16.6 SW19.2 SW19.4 U92.2(GND) U93.2(E1) U93.5(E2) U94.2(E1) U94.5(E2) U106.2(E1) U106.5(E2) U107.3(GND) U108.2(GND) U109.2(E1) U109.5(E2) U110.2(GND) U111.2(E1) U111.5(E2) U112.2(GND) U113.2(E1) U113.5(E2) U114.2(GND) U115.2(GND) Y10.2(GND) Y11.2(GND) ; also on sheet 1 3 4 5 6 7 8 9
GND_CAGE: J73.21 J73.22 J73.23 J73.24 J73.25 J73.26 J73.27 J73.28 J73.29 J73.30 J73.31 J73.32 J73.33 J73.34 J73.35 J73.36 J73.37 J73.38 J73.39 J73.40 R542.1 R544.1
VCC_PRI: C690.1 R776.1 U114.5(OUT) Y10.4(VDD)
VCC_SEC: C695.1 R792.1 U115.5(OUT) Y11.4(VDD)
VDDA: J100.27 ; also on sheet 5 6 7
VDDD: J100.31 ; also on sheet 5 6
VDDO: J100.35 ; also on sheet 5 6 7 8
VDDRA_HS: J100.39 ; also on sheet 5 6
VDDRA_LS: J100.37 ; also on sheet 5 6
VDDRB_HS: J100.43 ; also on sheet 5 6
VDDRB_LS: J100.41 ; also on sheet 5 6
VDDT: J100.29 ; also on sheet 5 6
1P0V_A1: J100.9 ; also on sheet 3 5
1P0V_A2: J100.11 ; also on sheet 3 5
1P0V_D1: J100.13 ; also on sheet 3 5
1P0V_D2: J100.15 ; also on sheet 3 5
1P5V: J100.17 ; also on sheet 4 5
1P8V: J100.19 ; also on sheet 4 5
2P5V: J100.23 ; also on sheet 4 8
3P3V: C295.1 C298.1 C299.1 J100.25 L15.2 L16.2 R538.1 R540.1 R545.1 R547.1 R551.1 R559.1 R560.1 R561.1 R562.1 R563.1 R564.1 R772.2 R774.2 R786.2 R787.2 R790.2 R793.2 U92.5(VDD) ; also on sheet 4 7 8
3P3V_CLK: C685.1 C686.1 C687.1 C688.1 J100.45 R724.2 R725.2 R734.2 R742.2 U107.5(VCC) U108.5(VDD) U110.5(VDD) U112.5(VDD) ; also on sheet 4 5
3P3V_RX: C300.1 C301.1 J73.15(VCCR) L16.1 R558.1
3P3V_TX: C296.1 C297.1 J73.16(VCCT) L15.1 R539.1 R556.1 R557.1
/STATUS1: Q106.3(D) R707.2 R708.2
/STATUS1_B: R708.1 U106.6(B1)
A4N: C225.1 U1.J1(INA4N)
A4P: C223.1 U1.H1(INA4P)
A5N: C221.1 U1.L2(INA5N)
A5P: C219.1 U1.K2(INA5P)
A6N: C217.1 U1.M1(INA6N)
A6P: C215.1 U1.L1(INA6P)
A7N: C213.1 U1.M4(INA7N)
A7P: C211.1 U1.M3(INA7P)
CHA_CLKOUTN_CONNECTOR: J72.K35 ; also on sheet 9
CHA_CLKOUTP_CONNECTOR: J72.K34 ; also on sheet 9
CHB_CLKOUTN_CONNECTOR: J72.A34 ; also on sheet 9
CHB_CLKOUTP_CONNECTOR: J72.A35 ; also on sheet 9
CLK_/RST: R744.2 R746.2 U112.1(/RST)
CLK_/RST_B: R746.1 U113.6(B1)
CLK_DVDD: J100.57 R706.1 R707.1 R714.1 R715.1 R716.1 R717.1 R718.1 R719.1 R750.1 R751.1 R752.1 R753.1 ; also on sheet 5 6
CLK_RST: R745.2 R747.2 U112.3(RST)
CLK_RST_B: R747.1 U113.4(B2)
CLK_RST_PB: R742.1 R743.1 SW15.1 U112.4(/MR)
CLK_SPI_CLK/PIN4: R753.2 R757.2 U100.5(SCL_/_PIN4)
CLK_SPI_LE/PIN3: R752.2 R756.2 R758.2 U100.4(SCS_/_AD1_/_PIN3)
CLK_SPI_MISO/PIN2: R751.2 R755.2 U100.3(SDO_/_AD0_/_PIN2)
CLK_SPI_MOSI/PIN1: R750.2 R754.2 U100.2(SDI_/_SDA_/_PIN1)
CLK_VCC: J100.59 ; also on sheet 5 9
CLK_VDD_IN: J100.55 R778.2 ; also on sheet 5 6
CLK_VDD_OUTA: J100.51 ; also on sheet 5 6
CLK_VDD_OUTB: J100.53 ; also on sheet 5 6
CLK_VDD_PLL: J100.47 ; also on sheet 5 6
CLK_VDD_PLL_A: J100.49 ; also on sheet 5 6
D101_1: D101.1 Q105.3(D)
D101_2: D101.2 R705.1
D102_1: D102.1 U106.1(C1)
D102_2: D102.2 R710.1
D103_1: D103.1 U106.3(C2)
D103_2: D103.2 R711.1
D104_1: D104.1 U109.1(C1)
D104_2: D104.2 R732.2
D105_1: D105.1 U109.3(C2)
D105_2: D105.2 R733.2
D106_1: D106.1 U111.1(C1)
D106_2: D106.2 R740.2
D107_1: D107.1 U111.3(C2)
D107_2: D107.2 R741.2
D108_1: D108.1 U113.1(C1)
D108_2: D108.2 R748.2
D109_1: D109.1 U113.3(C2)
D109_2: D109.2 R749.2
DISABLE_SFP+_TX: JMP36.1 R556.2 U92.4(/MR)
ELF: C683.1 R703.1 U100.41(ELF)
ELF_RC: C682.1 R703.2
EXT_SPI_CLK/PIN4: JMP104.9 R763.1
EXT_SPI_LE1/PIN3: JMP104.7 R762.1
EXT_SPI_LE2: JMP104.11 R764.1
EXT_SPI_MISO/PIN2: JMP104.5 R761.1
EXT_SPI_MOSI/PIN1: JMP104.3 R760.1
EXT_STATUS1/PIN0: JMP104.1 R759.1
HSRXAN: J73.12(RDN) U1.A12(HSRXAN)
HSRXAP: J73.13(RDP) U1.B12(HSRXAP)
HSRXBN: C249.1 U1.G12(HSRXBN)
HSRXBN_SMA: C249.2 J8.1(CENTER)
HSRXBP: C247.1 U1.H12(HSRXBP)
HSRXBP_SMA: C247.2 J7.1(CENTER)
HSTXAN: J73.19(TDN) U1.E12(HSTXAN)
HSTXAP: J73.18(TDP) U1.D12(HSTXAP)
HSTXBN: R582.1 U1.L12(HSTXBN)
HSTXBN_SMA: J6.1(CENTER) R582.2
HSTXBP: R581.1 U1.K12(HSTXBP)
HSTXBP_SMA: J5.1(CENTER) R581.2
I2C_CLK_PDN: R723.1 U42.24(P27)
I2C_REF_SEL: R720.1 U42.19(P22)
I2C_RESET/PWR: R743.2 U42.23(P26)
I2C_SI_MODE0: R721.1 U42.20(P23)
I2C_SI_MODE1: R722.1 U42.21(P24)
I2C_STATUS0: R712.2 U42.17(P20)
I2C_STATUS1: R713.2 U42.18(P21)
I2C_SYNCN: R735.2 U42.22(P25)
INA0N: C224.1 U1.A3(INA0N)
INA0N_CONNECTOR: C224.2 J72.K30
INA0P: C222.1 U1.A4(INA0P)
INA0P_CONNECTOR: C222.2 J72.K31
INA1N: C220.1 U1.B1(INA1N)
INA1N_CONNECTOR: C220.2 J72.K22
INA1P: C218.1 U1.A1(INA1P)
INA1P_CONNECTOR: C218.2 J72.K23
INA2N: C216.1 U1.C2(INA2N)
INA2N_CONNECTOR: C216.2 J72.K10
INA2P: C214.1 U1.B2(INA2P)
INA2P_CONNECTOR: C214.2 J72.K11
INA3N: C212.1 U1.E1(INA3N)
INA3N_CONNECTOR: C212.2 J72.K2
INA3P: C210.1 U1.D1(INA3P)
INA3P_CONNECTOR: C210.2 J72.K3
INA4N_CONNECTOR: J72.A3
INA4P_CONNECTOR: J72.A2
INA5N_CONNECTOR: J72.A11
INA5P_CONNECTOR: J72.A10
INA6N_CONNECTOR: J72.A23
INA6P_CONNECTOR: J72.A22
INA7N_CONNECTOR: J72.A31
INA7P_CONNECTOR: J72.A30
INB0/A4N_CONNECTOR: C225.2
INB0/A4P_CONNECTOR: C223.2
INB1/A5N_CONNECTOR: C221.2
INB1/A5P_CONNECTOR: C219.2
INB2/A6N_CONNECTOR: C217.2
INB2/A6P_CONNECTOR: C215.2
INB3/A7N_CONNECTOR: C213.2
INB3/A7P_CONNECTOR: C211.2
LS_OK_IN_A_CONNECTOR: J72.K37 ; also on sheet 7
LS_OK_IN_B_CONNECTOR: J72.A37 ; also on sheet 7
LS_OK_OUT_A_CONNECTOR: J72.K39 ; also on sheet 7
LS_OK_OUT_B_CONNECTOR: J72.A39 ; also on sheet 7
MAIN_RESET: R724.1 U107.2(B) ; also on sheet 7
MDC_B2B_CON: J72.E3 ; also on sheet 8
MDIO_B2B_CON: J72.E1 ; also on sheet 8
MOD_DEF0_MODULE_DETECT: J73.6(MOD-DEF0_ABS) Q11.1(G) R559.2
MOD_DEF1_SCL: J73.5(MOD-DEF1_SCL) JMP105.1 R563.2
MOD_DEF2_SDA: J73.4(MOD-DEF2_SDA) JMP105.3 R562.2
MODULE_DETECT_D: D48.1 Q12.3(D)
MODULE_DETECT_G: Q11.3(D) Q12.1(G) R564.2
MODULE_DETECT_L: D48.2 R551.2
OUTA0N: R572.1 U1.A7(OUTA0N)
OUTA0N_CONNECTOR: J72.K27 R572.2
OUTA0P: R571.1 U1.A6(OUTA0P)
OUTA0P_CONNECTOR: J72.K26 R571.2
OUTA1N: R570.1 U1.B6(OUTA1N)
OUTA1N_CONNECTOR: J72.K19 R570.2
OUTA1P: R569.1 U1.B5(OUTA1P)
OUTA1P_CONNECTOR: J72.K18 R569.2
OUTA2N: R568.1 U1.C5(OUTA2N)
OUTA2N_CONNECTOR: J72.K15 R568.2
OUTA2P: R567.1 U1.C4(OUTA2P)
OUTA2P_CONNECTOR: J72.K14 R567.2
OUTA3N: R566.1 U1.E3(OUTA3N)
OUTA3N_CONNECTOR: J72.K7 R566.2
OUTA3P: R565.1 U1.F3(OUTA3P)
OUTA3P_CONNECTOR: J72.K6 R565.2
OUTA4N: R580.1 U1.H3(OUTA4N)
OUTA4N_CONNECTOR: J72.A6
OUTA4P: R579.1 U1.J3(OUTA4P)
OUTA4P_CONNECTOR: J72.A7
OUTA5N: R578.1 U1.K4(OUTA5N)
OUTA5N_CONNECTOR: J72.A14
OUTA5P: R577.1 U1.K5(OUTA5P)
OUTA5P_CONNECTOR: J72.A15
OUTA6N: R576.1 U1.L5(OUTA6N)
OUTA6N_CONNECTOR: J72.A18
OUTA6P: R575.1 U1.L6(OUTA6P)
OUTA6P_CONNECTOR: J72.A19
OUTA7N: R574.1 U1.M6(OUTA7N)
OUTA7N_CONNECTOR: J72.A26
OUTA7P: R573.1 U1.M7(OUTA7P)
OUTA7P_CONNECTOR: J72.A27
OUTB0/A4N_CONNECTOR: R580.2
OUTB0/A4P_CONNECTOR: R579.2
OUTB1/A5N_CONNECTOR: R578.2
OUTB1/A5P_CONNECTOR: R577.2
OUTB2/A6N_CONNECTOR: R576.2
OUTB2/A6P_CONNECTOR: R575.2
OUTB3/A7N_CONNECTOR: R574.2
OUTB3/A7P_CONNECTOR: R573.2
P_BIAS: C691.2 R778.1 R779.2 R780.1 R781.1
PDN: R717.2 R728.2 R729.2 U100.43(~{PDN})
PDN_/RST: R728.1 R730.2 U108.1(/RST)
PDN_/RST_B: R730.1 U109.6(B1)
PDN_RESET: R726.2 R727.2 U108.4(/MR)
PDN_RESET_AND: R727.1 U107.4(Y)
PDN_RST: R729.1 R731.2 U108.3(RST)
PDN_RST_B: R731.1 U109.4(B2)
PDN_SWITCH: R723.2 R725.1 R726.1 SW13.1 U107.1(A)
PRI_EN: R770.2 R772.1 R773.2 U114.3(EN)
PRI_LED: D110.2 R776.2
PRI_OSC_EN: R770.1 R771.1 R786.1 SW19.1 ; also on sheet 7
PRI_REF_IN_N: C693.1 R785.2
PRI_REF_IN_N_SMP: C693.2 J104.1 R783.1
PRI_REF_IN_P: C692.1 R784.2
PRI_REF_IN_P_SMP: C692.2 J103.1 R782.1
PRI_REFN: R781.2 R785.1 U100.9(PRI_REFN)
PRI_REFP: R777.2 R780.2 R784.1 U100.8(PRI_REFP)
PRI_STDBY: R771.2 R774.1 R775.2 Y10.1(STDBY)
PRI_XO: R777.1 Y10.3(OUT)
RATE_SEL_0: J73.7(RATE_SEL_0) R560.2 R795.1
RATE_SEL_1: J73.9(RATE_SEL_1) R561.2 R796.1
REF_SEL: R714.2 R720.2 SW16.1 U100.6(REF_SEL)
REG_CAP: C684.1 U100.40(REG_CAP)
RESET/PWR: R718.2 R744.1 R745.1 U100.44(~{RESET/PWR})
RX_LOS: J73.8(RX_LOS) R553.2 R558.2
RX_LOS_B: R553.1 U94.4(B2)
RX_LOS_C: D52.1 U94.3(C2)
RX_LOS_L: D52.2 R547.2
SEC_EN: R788.2 R790.1 R791.2 U115.3(EN)
SEC_LED: D111.2 R792.2
SEC_OSC_EN: R787.1 R788.1 R789.1 SW19.3 ; also on sheet 7
SEC_REFP: U100.11(SEC_REFP) Y11.3(OUT)
SEC_STDBY: R789.2 R793.1 R794.2 Y11.1(STDBY)
SI_MODE0: R715.2 R721.2 SW16.3 U100.1(SI_MODE0)
SI_MODE1: R716.2 R722.2 SW16.5 U100.47(SI_MODE1)
SPI_CLK: R768.1 ; also on sheet 8
SPI_CLK_SOURCE/PIN4: R757.1 R763.2 R768.2
SPI_LE1: R767.1 ; also on sheet 8
SPI_LE1_SOURCE/PIN3: R756.1 R762.2 R767.2
SPI_LE2: R769.1 ; also on sheet 8
SPI_LE2_SOURCE: R758.1 R764.2 R769.2
SPI_MISO: R766.1 ; also on sheet 8
SPI_MISO_SOURCE/PIN2: R755.1 R761.2 R766.2
SPI_MOSI: R765.1 ; also on sheet 8
SPI_MOSI_SOURCE/PIN1: R754.1 R760.2 R765.2
STATUS0: R704.1 R712.1 U100.46(STATUS0)
STATUS0_G: Q105.1(G) R704.2
STATUS1/PIN0: Q106.1(G) R706.2 R709.2 R713.1 R759.2 U100.45(STATUS1/PIN0)
STATUS1_B: R709.1 U106.4(B2)
SYNCN: R719.2 R736.1 R737.1 U100.42(~{SYNCN})
SYNCN_/RST: R736.2 R738.2 U110.1(/RST)
SYNCN_/RST_B: R738.1 U111.6(B1)
SYNCN_PB: R734.1 R735.1 SW14.1 U110.4(/MR)
SYNCN_RST: R737.2 R739.2 U110.3(RST)
SYNCN_RST_B: R739.1 U111.4(B2)
TX_DISABLE: J73.3(TX_DISABLE) R539.2 R541.1 R543.1
TX_DISABLE_/RST: R541.2 R546.2 U92.1(/RST)
TX_DISABLE_/RST_B: R546.1 U93.6(B1)
TX_DISABLE_/RST_C: D49.1 U93.1(C1)
TX_DISABLE_/RST_L: D49.2 R538.2
TX_DISABLE_RST: R543.2 R548.2 U92.3(RST)
TX_DISABLE_RST_B: R548.1 U93.4(B2)
TX_DISABLE_RST_C: D50.1 U93.3(C2)
TX_DISABLE_RST_L: D50.2 R540.2
TX_FAULT: J73.2(TX_FAULT) R549.2 R557.2
TX_FAULT_B: R549.1 U94.6(B1)
TX_FAULT_C: D51.1 U94.1(C1)
TX_FAULT_L: D51.2 R545.2

Not connected (* = marked no-connect by the designer): J72 1(MOUNT1)* 2(MOUNT2)* 3(MOUNT3)* 4(MOUNT4)* C1* C3* C5* C6* C7* C8* C9* C10* C11* C12* C13* C14* C15* C16* C17* C18* C19* C20* C21* C22* C23* C24* C25* C26* C27* C28* C29* C30* C31* C32* C33* C34* C35* C36* C37* C38* C39* C40* D5* D6* D7* D8* D9* D10* D11* D12* D13* D14* D15* D16* D17* D18* D19* D20* D21* D22* D23* D24* D25* D26* D27* D28* D29* D30* D31* D32* D33* D34* D35* D36* D37* D38* D39* D40* E5* E6* E7* E8* E9* E10* E11* E12* E13* E14* E15* E16* E17* E18* E19* E20* E21* E22* E23* E24* E25* E26* E27* E28* E29* E30* E31* E32* E33* E34* E35* E36* E37* E38* E39* E40* F5* F6* F7* F8* F9* F10* F11* F12* F13* F14* F15* F16* F17* F18* F19* F20* F21* F22* F23* F24* F25* F26* F27* F28* F29* F30* F31* F32* F33* F34* F35* F36* F37* F38* F39* F40* G1* G3* G5* G6* G7* G8* G9* G10* G11* G12* G13* G14* G15* G16* G17* G18* G19* G20* G21* G22* G23* G24* G25* G26* G27* G28* G29* G30* G31* G32* G33* G34* G35* G36* G37* G38* G39* G40* H5* H6* H7* H8* H9* H10* H11* H12* H13* H14* H15* H16* H17* H18* H19* H20* H21* H22* H23* H24* H25* H26* H27* H28* H29* H30* H31* H32* H33* H34* H35* H36* H37* H38* H39* H40*; SW16 7* 8*; U100 12(SEC_REFN)*; U114 4(NC)*; U115 4(NC)*

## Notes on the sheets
sheet 10
- (STATUS 1) PRIMARY REFERENCE LED
- (STATUS 1) SECONDARY REFERENCE LED
- (STATUS 0) PLL LOCK LED
- SPI INTERFACE
- PRIMARY/SECONDARY REFERENCE
  INDICATOR REQUIRES SETTING
  CDCM6208 REGISTER R3.12:10
  TO "100"
- LOOP FILTER
- DO NOT OVERLAP RESISTOR PADS
- CLOCK /PDN LED
- CLOCK PDN LED
- VOLTAGE SUPERVISOR
  AND RESET MONITOR
- I2C-TO-GPIO
  OUTPUT PINS
- CLOCK PDN
  PUSHBUTTON
- AND GATE USED TO CONNECT
  AND ISOLATE MAIN RESET
  WITH CLOCK POWER DOWN TO
  RESET REGISTER MAP
- CLOCK /RESET LED
- CLOCK RESET LED
- CLOCK /RESET LED
- CLOCK RESET LED
- VOLTAGE SUPERVISOR
  AND RESET MONITOR
- CLOCK RESET
  PUSHBUTTON
- VOLTAGE SUPERVISOR
  AND RESET MONITOR
- CLOCK SYNCN
  PUSHBUTTON
sheet 11
- NOTE:
     1.  MATCH LOW SPEED INPUT AND OUTPUT TRACE LENGTHS TO EACHOTHER
     2.  MATCH HIGH SPEED TRANSMIT AND RECEIVE TRACE LENGTHS TO EACHOTHER
sheet 12
- RESISTORS ARE USED TO PROVIDE
  COMMON PATH TO GROUND.  PLACE
  ONE ON EACH SIDE OF OPTICAL
  MODULE CAGE NEAR THE MIDDLE OF
  THE MODULE.
- THE HIGH SPEED TX LINES SHOULD BE AC COUPLED IN
  THE SYSTEM WITH 0.1uF CAPACITORS FOR PROPER
  OPERATION.  ZERO OHM RESISTORS ARE INSTALLED ON
  THIS BOARD TO ALLOW FOR EXTERNAL LOOPBACK BETWEEN
  THE HSTXB AND HSRXB UTILIZING THE AC CAPACITORS
  ON THE HSRXB PINS. THE ZERO OHM RESISTORS CAN BE
  REPLACED WITH 0.1uF CAPACITORS IF AC COUPLING
  CAPACITORS ARE NEEDED ON THESE SIGNALS.
sheet 13
- NOTE:
- PLACE R780, AND R781
  AS CLOSE AS POSSIBLE
  TO THE PINS ON U2.
  THESE ARE TERMINATION
  RESISTORS
- OVERLAP RESISTOR PADS
  OF R777 AND R784.
sheet 14
- NOTE:
- NOTE:
  PLACE DECOULING CAPS NEAR J100 CONNECTOR
